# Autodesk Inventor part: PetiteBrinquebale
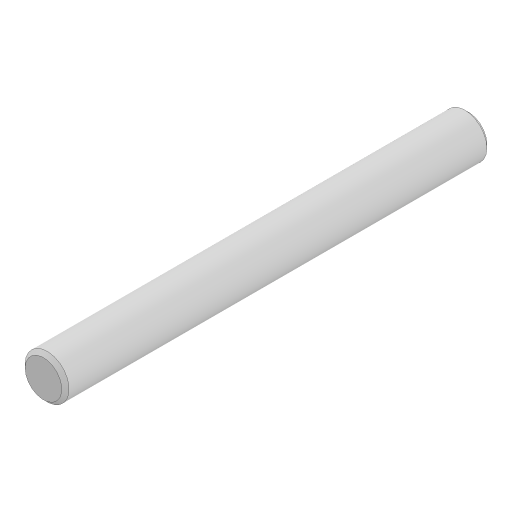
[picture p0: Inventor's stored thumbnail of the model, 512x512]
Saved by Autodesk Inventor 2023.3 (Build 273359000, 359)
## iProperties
Created: 2024-11
Part Number: PetiteBrinquebale
Material: Générique
Description: STEP AP203
Document SubType Name: Modeling
Designer: Thier
Density: 1 g/cm^3
Appearance: Par défaut
Title: PetiteBrinquebale.STEP
Revision Number: ANY
Sending System: SolidWorks 2017
Preprocessor: SwSTEP 2.0
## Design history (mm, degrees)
feature "Chanfrein1"
node "Solide1"
